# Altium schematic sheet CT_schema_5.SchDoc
size 287 x 160 mm
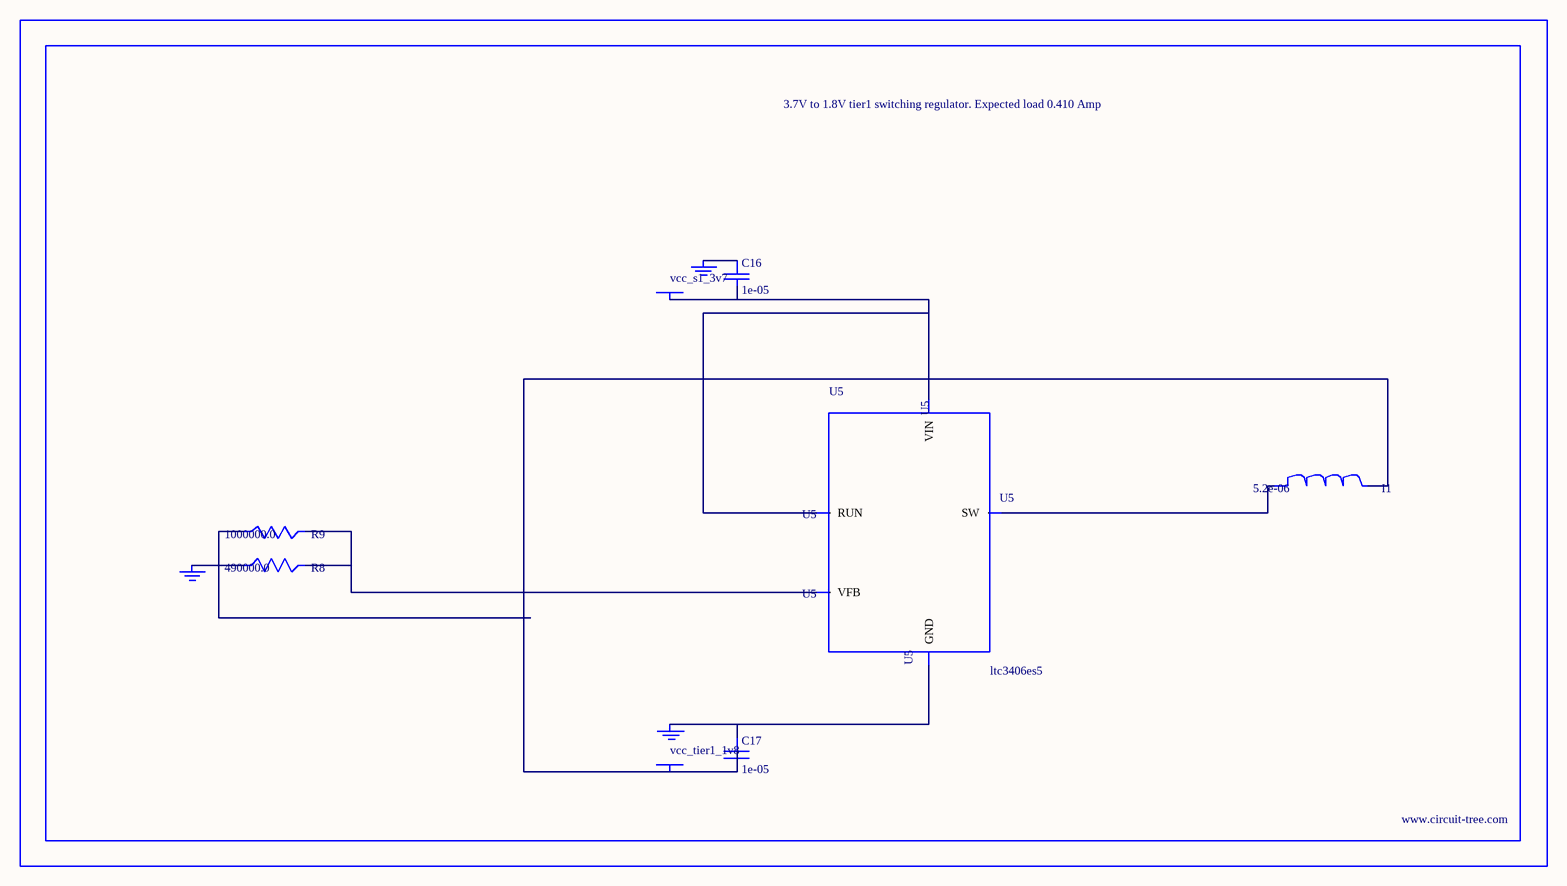
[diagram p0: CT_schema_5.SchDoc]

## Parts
BORDER4  (no value)
C16  1e-05  [C0805]
C17  1e-05  [C0805]
GND_INSTANCE_4_0  (no value)
GND_INSTANCE_4_1  (no value)
GND_INSTANCE_4_2  (no value)
I1  5.2e-06  [DR1040]
POWER_INSTANCE_4_0  vcc_tier1_1v8
POWER_INSTANCE_4_1  vcc_s1_3v7
R8  490000.0  [R0603]
R9  1000000.0  [R0603]
U5  ltc3406es5  [TSOT-23-5]

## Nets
NetC16_1: C16.1 GND_INSTANCE_4_1.0(GND)
NetC16_2: C16.2 POWER_INSTANCE_4_1.0(PWR) U5.1(RUN) U5.4(VIN)
NetC17_1: C17.1 GND_INSTANCE_4_0.0(GND) U5.2(GND)
NetC17_2: C17.2 I1.2 POWER_INSTANCE_4_0.0(PWR) R9.1
NetGND_INSTANCE_4_2_0: GND_INSTANCE_4_2.0(GND) R8.1
NetI1_1: I1.1 U5.3(SW)
NetR8_2: R8.2 R9.2 U5.5(VFB)

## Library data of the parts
BORDER4 = BORDER_PAGE4
C16 C17 = C0805C106K8RACTU
GND_INSTANCE_4_0-GND_INSTANCE_4_2 = GND
I1 = DR1040-5R2-R
POWER_INSTANCE_4_0 POWER_INSTANCE_4_1 = PWR
R8 = R8
R9 = RC0603JR-071ML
